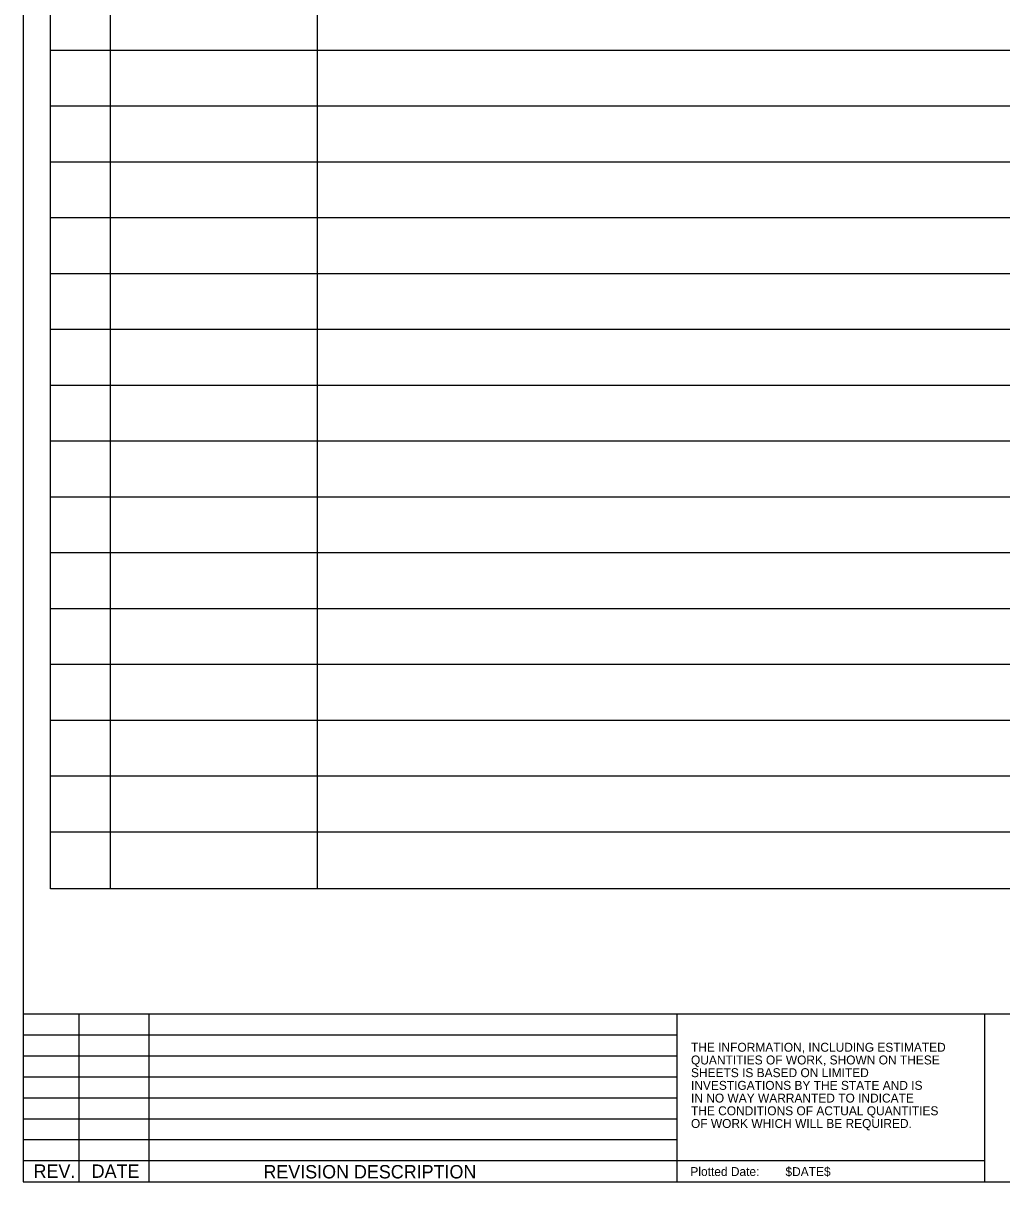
# Model space of a CAD drawing. Extents: x 0 to 5.28, y 0 to 1.73.
# Drawn here: x 0 to 0.731, y 0 to 0.865 of the extents above; entities that cross this region are included whole.
import ezdxf

# ---------------------------------------------------------------- set-up
doc = ezdxf.new("R2010")
doc.units = 0
for name, color, linetype in [('CT_Bdr_Txt_Titleblock', 7, 'Continuous'), ('CT_Border_Perimeter_Shape', 7, 'Continuous'), ('CT_Dimensions', 7, 'Continuous'), ('CT_Disclaimer_Text', 7, 'Continuous'), ('CT_List_of _Standards', 7, 'Continuous'), ('CT_Locked', 7, 'Continuous'), ('CT_Title_Block_Linework', 7, 'Continuous'), ('CT_Title_Block_Text', 7, 'Continuous')]:
    doc.layers.add(name, color=color, linetype=linetype)

msp = doc.modelspace()

# ---------------------------------------------------------------- linework, layer by layer
at = {"layer": 'CT_Bdr_Txt_Titleblock'}
msp.add_line((0, 0), (0, 0), dxfattribs=at)
msp.add_line((0, 0), (0, 0), dxfattribs=at)
msp.add_line((0, 0), (0, 0), dxfattribs=at)
at = {"layer": 'CT_Border_Perimeter_Shape'}
msp.add_lwpolyline([(0, 0), (2.64583, 0), (2.64583, 1.72917), (0, 1.72917)], close=True, dxfattribs=at)
at = {"layer": 'CT_Dimensions'}
msp.add_lwpolyline([(0.02045, 1.66667), (1.28923, 1.66667), (1.28923, 0.21875), (0.02045, 0.21875)], close=True, dxfattribs=at)
msp.add_lwpolyline([(0.02045, 1.66667), (1.28923, 1.66667), (1.28923, 0.21875), (0.02045, 0.21875)], close=True, dxfattribs=at)
at = {"layer": 'CT_List_of _Standards'}
for p, q in [((0.06506, 1.66667), (0.06506, 0.21875)), ((0.2196, 1.66667), (0.2196, 0.21875)), ((0.02045, 0.8445), (1.29167, 0.8445)), ((0.02045, 0.8445), (1.29167, 0.8445)), ((0.02045, 0.80283), (1.29167, 0.80283)), ((0.02045, 0.80283), (1.29167, 0.80283)), ((0.02045, 0.76116), (1.29167, 0.76116)), ((0.02045, 0.76116), (1.29167, 0.76116)), ((0.02045, 0.76116), (1.29167, 0.76116)), ((0.02045, 0.7195), (1.29167, 0.7195)), ((0.02045, 0.7195), (1.29167, 0.7195)), ((0.02045, 0.67783), (1.29167, 0.67783)), ((0.02045, 0.67783), (1.29167, 0.67783)), ((0.02045, 0.63616), (1.29167, 0.63616)), ((0.02045, 0.63616), (1.29167, 0.63616)), ((0.02045, 0.5945), (1.29167, 0.5945)), ((0.02045, 0.5945), (1.29167, 0.5945)), ((0.02045, 0.55283), (1.29167, 0.55283)), ((0.02045, 0.55283), (1.29167, 0.55283)), ((0.02045, 0.51116), (1.29167, 0.51116)), ((0.02045, 0.51116), (1.29167, 0.51116)), ((0.02045, 0.4695), (1.29167, 0.4695)), ((0.02045, 0.4695), (1.29167, 0.4695)), ((0.02045, 0.42783), (1.29167, 0.42783)), ((0.02045, 0.42783), (1.29167, 0.42783)), ((0.02045, 0.38616), (1.29167, 0.38616)), ((0.02045, 0.38616), (1.29167, 0.38616)), ((0.02045, 0.38616), (1.29167, 0.38616)), ((0.02045, 0.3445), (1.29167, 0.3445)), ((0.02045, 0.3445), (1.29167, 0.3445)), ((0.02045, 0.30283), (1.29167, 0.30283)), ((0.02045, 0.30283), (1.29167, 0.30283)), ((0.02045, 0.26116), (1.29167, 0.26116)), ((0.02045, 0.26116), (1.29167, 0.26116))]:
    msp.add_line(p, q, dxfattribs=at)
at = {"layer": 'CT_Locked'}
msp.add_line((0, 0), (0, 0), dxfattribs=at)
msp.add_line((0, 0), (0, 0), dxfattribs=at)
msp.add_line((0, 0), (0, 0), dxfattribs=at)
at = {"layer": 'CT_Title_Block_Linework'}
for p, q in [((2.64583, 0.125), (0, 0.125)), ((0.04167, 0.125), (0.04167, 0)), ((0.09375, 0.125), (0.09375, 0)), ((0.48815, 0.125), (0.48815, 0)), ((0.71781, 0.125), (0.71781, 0)), ((0.71781, 0.125), (0.71781, 0)), ((0.48815, 0.10938), (0, 0.10938)), ((0.48815, 0.09375), (0, 0.09375)), ((0.48815, 0.07813), (0, 0.07813)), ((0.48815, 0.0625), (0, 0.0625)), ((0.48815, 0.04688), (0, 0.04688)), ((0.48815, 0.03125), (0, 0.03125)), ((0.71781, 0.01563), (0, 0.01563))]:
    msp.add_line(p, q, dxfattribs=at)

# ---------------------------------------------------------------- texts
at = {"layer": 'CT_Disclaimer_Text'}
for s, p in [('THE INFORMATION, INCLUDING ESTIMATED ', (0.49865, 0.09707)), ('QUANTITIES OF WORK, SHOWN ON THESE ', (0.49865, 0.08759)), ('SHEETS IS BASED ON LIMITED ', (0.49865, 0.07811)), ('INVESTIGATIONS BY THE STATE AND IS', (0.49865, 0.06864)), ('IN NO WAY WARRANTED TO INDICATE ', (0.49865, 0.05916)), ('THE CONDITIONS OF ACTUAL QUANTITIES ', (0.49865, 0.04968)), ('OF WORK WHICH WILL BE REQUIRED.', (0.49865, 0.0402))]:
    msp.add_text(s, height=0.0066667, dxfattribs=at).set_placement(p)
at = {"layer": 'CT_Title_Block_Text'}
for s, p in [('REV.', (0.00776, 0.00297)), ('DATE', (0.05115, 0.00297)), ('REVISION DESCRIPTION', (0.17938, 0.00252))]:
    msp.add_text(s, height=0.01, dxfattribs=at).set_placement(p)
for s, height, p in [('Plotted Date:', 0.0066667, (0.49821, 0.00428)), ('$DATE$', 0.006667, (0.56921, 0.00426))]:
    msp.add_text(s, height=height, rotation=0.125, dxfattribs=at).set_placement(p)

doc.saveas('drawing.dxf')
